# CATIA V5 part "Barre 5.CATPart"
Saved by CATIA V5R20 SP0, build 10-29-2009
Part number: Barre 5
Bounding box of the stored display mesh (mm): x 224.923 to 244.923, y -228.208 to 211.792, z 0 to 10
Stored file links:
  C:\Users\Matthieu\Desktop\IFMA\Cours 2A\Thinkmotion\Projet_IAO_714_Matthieu_Perrusset\Barre 5.CATPart
  C:\Users\Matthieu\Desktop\IFMA\Cours 2A\Thinkmotion\Ass_skl_IAO.CATProduct
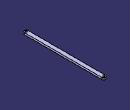
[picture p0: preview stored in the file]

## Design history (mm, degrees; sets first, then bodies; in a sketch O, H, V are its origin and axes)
AxisSystem1: origin (0, 0, 0), X (1, 0, 0), Y (0, 1, 0), Z (0, 0, 1)
Set1
  Plane1 "Plan_Ref": linked copy from another document
  Line1 "Barre_5": linked copy from another document
  Line2 "Axe_Pivot_b5b4": linked copy from another document
  Line3 "Axe_Pivot_b5b6": linked copy from another document
Body1 (main body)
  Sketch1 on Plane1, origin (0, 0, 0), H (1, 0, 0), V (0, 1, 0)
    line L1 (244.9232, 201.7919) -> (244.9232, -218.2081)
    arc A1 centre (234.9232, -218.2081) radius 10 from (244.9232, -218.2081) to (224.9232, -218.2081) cw
    point P3 (234.9232, -218.2081)
    line L2 (224.9232, -218.2081) -> (224.9232, 201.7919)
    arc A2 centre (234.9232, 201.7919) radius 10 from (224.9232, 201.7919) to (244.9232, 201.7919) cw
    point P6 (234.9232, 201.7919)
    point P7 (244.9232, 201.7919)
    reference projected line E1 (234.9232, 201.7919) -> (234.9232, -218.2081) from Line1
    reference projected line E2 (234.9232, 201.7919) -> (234.9232, -218.2081) from Line1
    reference projected point E3 (234.9232, 201.7919) from Line2
    reference projected line E4 (234.9232, 201.7919) -> (234.9232, -218.2081) from Line1
    reference projected line E5 (234.9232, 201.7919) -> (234.9232, -218.2081) from Line1
    reference projected point E6 (234.9232, -218.2081) from Line3
    circle A3 centre (234.9232, -218.2081) radius 5
    circle A4 centre (234.9232, 201.7919) radius 5
    distance P6 A2 = 10
    distance E4 L1 = 10
    distance E5 L2 = 10
    distance P3 A1 = 10
    distance A3 P3 = 5
    distance A4 P6 = 5
    vertical: L1 V, L2 V
    coincidence: A2 P7, P7 L1, P6 E3, E6 P3
    parallelism: E1 L1, L2 E2
  Pad1: profile Sketch1, direction (0, 0, 1), length 10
